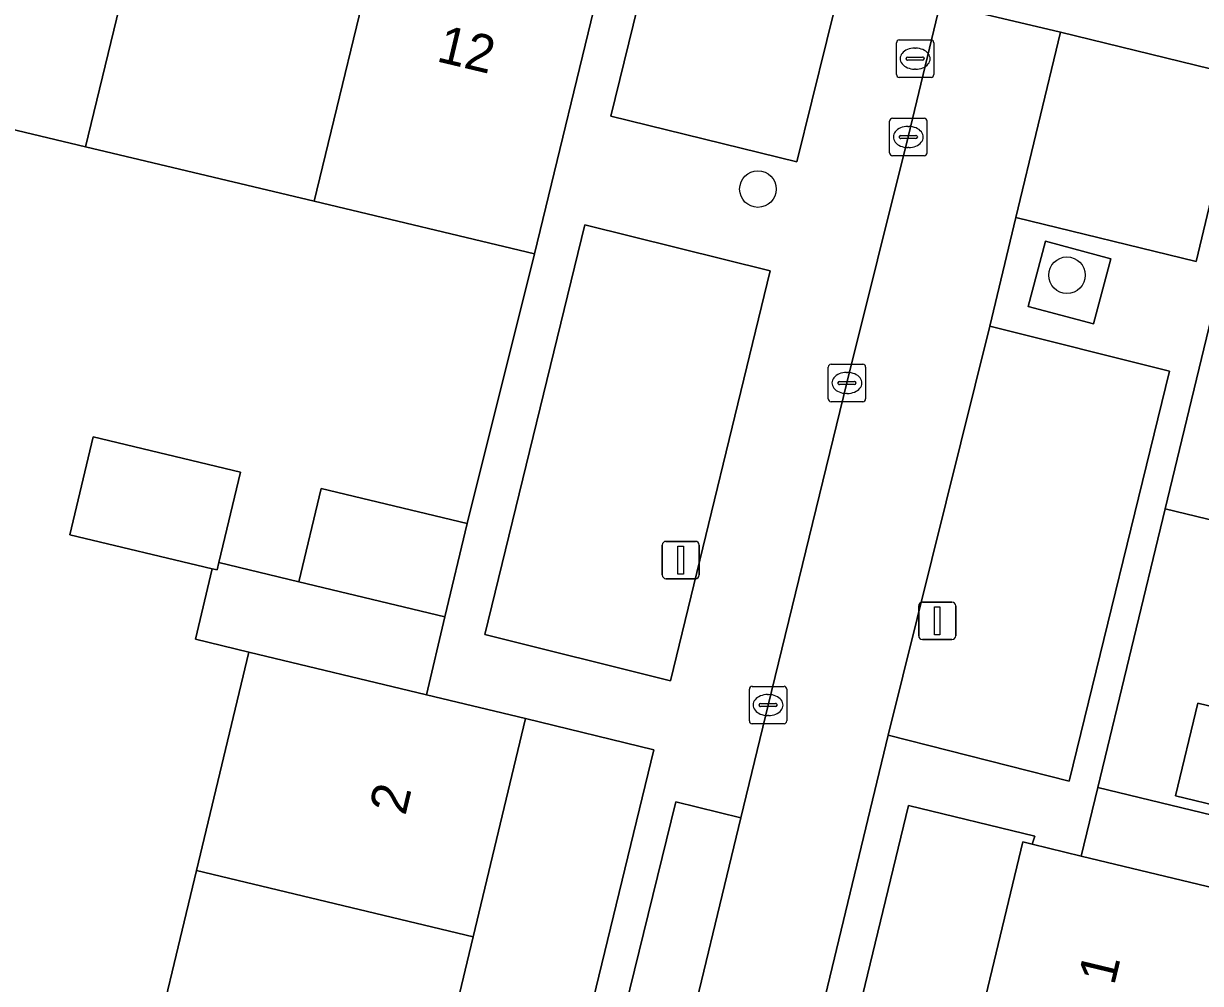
# Model space of a CAD drawing. Extents: x 162803 to 163818, y 381639 to 382475.
# Drawn here: x 163134.3 to 163165.81, y 382302.82 to 382328.5 of the extents above; entities that cross this region are included whole.
import ezdxf

# ---------------------------------------------------------------- set-up
doc = ezdxf.new("R2010")
doc.units = 0
for name, color, linetype in [('IMGEO_Boom', 7, 'Continuous'), ('IMGEO_Erf', 7, 'Continuous'), ('IMGEO_Groenvoorziening', 7, 'Continuous'), ('IMGEO_Kolk', 7, 'Continuous'), ('IMGEO_Lichtmast', 7, 'Continuous'), ('IMGEO_Muur', 7, 'Continuous'), ('IMGEO_Pand', 7, 'Continuous'), ('IMGEO_Pand_nummerreeks', 7, 'Continuous'), ('IMGEO_Parkeervlak_open', 7, 'Continuous'), ('IMGEO_Rijbaan_lokaal_open', 7, 'Continuous'), ('IMGEO_Rioolput', 7, 'Continuous'), ('IMGEO_Voetpad_open', 7, 'Continuous')]:
    doc.layers.add(name, color=color, linetype=linetype)

msp = doc.modelspace()

# ---------------------------------------------------------------- linework, layer by layer
at = {"layer": 'IMGEO_Boom'}
for centre in [(163153.96, 382324.072), (163162.234, 382321.768)]:
    msp.add_circle(centre, 0.489, dxfattribs=at)
at = {"layer": 'IMGEO_Erf'}
for points in [[(163137.51, 382299.932), (163138.927, 382305.841), (163140.328, 382311.683), (163138.901, 382312.025), (163139.353, 382313.911), (163135.54, 382314.821), (163136.165, 382317.441), (163140.107, 382316.5), (163139.53, 382314.08), (163141.667, 382313.567), (163142.265, 382316.061), (163146.18, 382315.122), (163147.979, 382322.337), (163142.076, 382323.745), (163135.958, 382325.205), (163130.086, 382326.605)], [(163170.946, 382314.044), (163164.865, 382315.515), (163163.061, 382308.056), (163184.008, 382302.99)], [(163137.011, 382250.814), (163151.17, 382309.066), (163147.739, 382309.906), (163146.338, 382304.063), (163144.921, 382298.154), (163143.552, 382292.448), (163142.148, 382286.591), (163140.708, 382280.587), (163139.316, 382274.782), (163137.911, 382268.926), (163136.518, 382263.116), (163135.102, 382257.214)]]:
    msp.add_lwpolyline(points, dxfattribs=at)
for points in [[(163169.129, 382306.875), (163165.137, 382307.839), (163165.736, 382310.318), (163169.728, 382309.354)], [(163154.012, 382277.422), (163155.425, 382283.276), (163156.897, 382289.378), (163158.25, 382294.983), (163159.675, 382300.888), (163161.054, 382306.603), (163161.303, 382306.543), (163161.374, 382306.761), (163157.996, 382307.58), (163144.039, 382250), (163143.732, 382248.734), (163146.893, 382247.921), (163147.395, 382250), (163148.351, 382253.961), (163149.715, 382259.613), (163151.151, 382265.563), (163152.6, 382271.569)]]:
    msp.add_lwpolyline(points, close=True, dxfattribs=at)
at = {"layer": 'IMGEO_Groenvoorziening'}
msp.add_lwpolyline([(163162.944, 382320.464), (163163.411, 382322.207), (163161.661, 382322.676), (163161.194, 382320.933)], close=True, dxfattribs=at)
at = {"layer": 'IMGEO_Kolk'}
for p, q in [((163157.486, 382325.04), (163157.486, 382325.892)), ((163157.561, 382325.966), (163158.413, 382325.966)), ((163158.487, 382325.892), (163158.487, 382325.04)), ((163157.788, 382325.509), (163158.186, 382325.509)), ((163157.974, 382325.746), (163157.999, 382325.746)), ((163157.745, 382325.46), (163157.745, 382325.472)), ((163158.183, 382325.423), (163157.785, 382325.423)), ((163158.229, 382325.472), (163158.229, 382325.46)), ((163158.413, 382324.966), (163157.561, 382324.966)), ((163157.997, 382325.186), (163157.972, 382325.186)), ((163155.843, 382318.458), (163155.843, 382319.31)), ((163155.918, 382319.384), (163156.77, 382319.384)), ((163156.844, 382319.31), (163156.844, 382318.458)), ((163156.102, 382318.878), (163156.102, 382318.89)), ((163156.145, 382318.927), (163156.543, 382318.927)), ((163156.331, 382319.164), (163156.356, 382319.164)), ((163156.586, 382318.89), (163156.586, 382318.878)), ((163156.54, 382318.841), (163156.142, 382318.841)), ((163156.354, 382318.604), (163156.329, 382318.604)), ((163156.77, 382318.384), (163155.918, 382318.384)), ((163153.807, 382310.767), (163154.659, 382310.767)), ((163153.732, 382309.841), (163153.732, 382310.693)), ((163154.22, 382310.547), (163154.245, 382310.547)), ((163154.733, 382310.693), (163154.733, 382309.841)), ((163153.991, 382310.261), (163153.991, 382310.273)), ((163154.429, 382310.224), (163154.031, 382310.224)), ((163154.034, 382310.31), (163154.432, 382310.31)), ((163154.475, 382310.273), (163154.475, 382310.261)), ((163154.659, 382309.767), (163153.807, 382309.767)), ((163154.243, 382309.987), (163154.218, 382309.987))]:
    msp.add_line(p, q, dxfattribs=at)
for points in [[(163157.486, 382325.04), (163157.486, 382325.892)], [(163157.561, 382325.966), (163158.413, 382325.966)], [(163158.487, 382325.892), (163158.487, 382325.04)], [(163158.413, 382324.966), (163157.561, 382324.966)], [(163155.843, 382318.458), (163155.843, 382319.31)], [(163155.918, 382319.384), (163156.77, 382319.384)], [(163156.844, 382319.31), (163156.844, 382318.458)], [(163156.77, 382318.384), (163155.918, 382318.384)], [(163153.807, 382310.767), (163154.659, 382310.767)], [(163153.732, 382309.841), (163153.732, 382310.693)], [(163154.733, 382310.693), (163154.733, 382309.841)], [(163154.659, 382309.767), (163153.807, 382309.767)]]:
    msp.add_lwpolyline(points, dxfattribs=at)
for centre, radius, start, end in [((163157.563, 382325.89), 0.0765, 91.552, 178.448), ((163157.563, 382325.89), 0.0765, 91.552, 178.448), ((163158.411, 382325.89), 0.0765, 1.552, 88.448), ((163158.411, 382325.89), 0.0765, 1.552, 88.448), ((163157.785, 382325.469), 0.0403, 85.8775, 175.7526), ((163158.19, 382325.471), 0.0386, 1.7309, 96.639), ((163157.782, 382325.459), 0.0366, 178.938, 274.7102), ((163158.186, 382325.466), 0.043, 264.8664, 352.4533), ((163157.563, 382325.042), 0.0765, 181.552, 268.448), ((163157.563, 382325.042), 0.0765, 181.552, 268.448), ((163158.411, 382325.042), 0.0765, 271.552, 358.448), ((163158.411, 382325.042), 0.0765, 271.552, 358.448), ((163155.92, 382319.308), 0.0765, 91.552, 178.448), ((163155.92, 382319.308), 0.0765, 91.552, 178.448), ((163156.768, 382319.308), 0.0765, 1.552, 88.448), ((163156.768, 382319.308), 0.0765, 1.552, 88.448), ((163156.142, 382318.887), 0.0403, 85.8775, 175.7526), ((163156.547, 382318.889), 0.0386, 1.7309, 96.639), ((163156.139, 382318.877), 0.0366, 178.938, 274.7102), ((163156.543, 382318.884), 0.043, 264.8664, 352.4533), ((163155.92, 382318.46), 0.0765, 181.552, 268.448), ((163155.92, 382318.46), 0.0765, 181.552, 268.448), ((163156.768, 382318.46), 0.0765, 271.552, 358.448), ((163156.768, 382318.46), 0.0765, 271.552, 358.448), ((163153.809, 382310.691), 0.0765, 91.552, 178.448), ((163153.809, 382310.691), 0.0765, 91.552, 178.448), ((163154.657, 382310.691), 0.0765, 1.552, 88.448), ((163154.657, 382310.691), 0.0765, 1.552, 88.448), ((163154.031, 382310.27), 0.0403, 85.8775, 175.7526), ((163154.028, 382310.26), 0.0366, 178.938, 274.7102), ((163154.432, 382310.267), 0.043, 264.8664, 352.4533), ((163154.436, 382310.272), 0.0386, 1.7309, 96.639), ((163153.809, 382309.843), 0.0765, 181.552, 268.448), ((163153.809, 382309.843), 0.0765, 181.552, 268.448), ((163154.657, 382309.843), 0.0765, 271.552, 358.448), ((163154.657, 382309.843), 0.0765, 271.552, 358.448)]:
    msp.add_arc(centre, radius, start, end, dxfattribs=at)
for centre, major_axis, ratio, start_param, end_param in [((163157.973, 382325.466), (-0.387, 0.002), 0.722429, 4.712389, 7.853982), ((163157.998, 382325.466), (-0.39, 0.002), 0.717154, 1.570796, 4.712389), ((163156.33, 382318.884), (-0.387, 0.002), 0.722429, 4.712389, 7.853982), ((163156.355, 382318.884), (-0.39, 0.002), 0.717154, 1.570796, 4.712389), ((163154.219, 382310.267), (-0.387, 0.002), 0.722429, 4.712389, 7.853982), ((163154.244, 382310.267), (-0.39, 0.002), 0.717154, 1.570796, 4.712389)]:
    msp.add_ellipse(centre, major_axis=major_axis, ratio=ratio, start_param=start_param, end_param=end_param, dxfattribs=at)
at = {"layer": 'IMGEO_Lichtmast'}
for p, q in [((163151.399, 382313.747), (163151.399, 382314.547)), ((163151.399, 382314.547), (163151.399, 382313.747)), ((163151.499, 382314.647), (163152.289, 382314.647)), ((163152.289, 382314.647), (163151.499, 382314.647)), ((163152.389, 382314.547), (163152.389, 382313.747)), ((163152.389, 382313.747), (163152.389, 382314.547)), ((163152.289, 382313.647), (163151.499, 382313.647)), ((163151.499, 382313.647), (163152.289, 382313.647)), ((163158.265, 382312.12), (163158.265, 382312.92)), ((163158.265, 382312.92), (163158.265, 382312.12)), ((163158.365, 382313.02), (163159.155, 382313.02)), ((163159.155, 382313.02), (163158.365, 382313.02)), ((163159.255, 382312.92), (163159.255, 382312.12)), ((163159.255, 382312.12), (163159.255, 382312.92)), ((163159.155, 382312.02), (163158.365, 382312.02)), ((163158.365, 382312.02), (163159.155, 382312.02))]:
    msp.add_line(p, q, dxfattribs=at)
for points in [[(163151.819, 382314.522), (163151.969, 382314.522), (163151.969, 382313.772), (163151.819, 382313.772), (163151.819, 382314.522)], [(163158.685, 382312.895), (163158.835, 382312.895), (163158.835, 382312.145), (163158.685, 382312.145), (163158.685, 382312.895)]]:
    msp.add_lwpolyline(points, dxfattribs=at)
for centre, start, end in [((163151.499, 382314.547), 90, 180), ((163151.499, 382314.547), 90, 180), ((163152.289, 382314.547), 0, 90), ((163152.289, 382314.547), 360, 90), ((163151.499, 382313.747), 180, 270), ((163151.499, 382313.747), 180, 270), ((163152.289, 382313.747), 270, 0), ((163152.289, 382313.747), 270, 0), ((163158.365, 382312.92), 90, 180), ((163158.365, 382312.92), 90, 180), ((163159.155, 382312.92), 0, 90), ((163159.155, 382312.92), 360, 90), ((163158.365, 382312.12), 180, 270), ((163158.365, 382312.12), 180, 270), ((163159.155, 382312.12), 270, 0), ((163159.155, 382312.12), 270, 0)]:
    msp.add_arc(centre, 0.1, start, end, dxfattribs=at)
at = {"layer": 'IMGEO_Muur'}
for points in [[(163146.18, 382315.122), (163147.979, 382322.337)], [(163164.865, 382315.515), (163163.126, 382308.325)]]:
    msp.add_lwpolyline(points, dxfattribs=at)
at = {"layer": 'IMGEO_Pand'}
for points in [[(163137.772, 382332.67), (163131.9, 382334.068), (163130.086, 382326.605), (163135.958, 382325.205)], [(163137.772, 382332.67), (163135.958, 382325.205), (163142.076, 382323.745), (163143.891, 382331.212)], [(163143.891, 382331.212), (163142.076, 382323.745), (163147.979, 382322.337), (163149.794, 382329.806)], [(163173.371, 382324.081), (163167.289, 382325.55), (163165.508, 382318.171), (163164.865, 382315.515), (163170.946, 382314.044), (163171.589, 382316.702)], [(163135.54, 382314.821), (163139.353, 382313.911), (163139.482, 382313.88), (163139.53, 382314.08), (163140.107, 382316.5), (163136.165, 382317.441)], [(163145.582, 382312.628), (163146.18, 382315.122), (163142.265, 382316.061), (163141.667, 382313.567)], [(163138.927, 382305.841), (163146.338, 382304.063), (163147.739, 382309.906), (163145.083, 382310.543), (163140.328, 382311.683)], [(163169.129, 382306.875), (163169.728, 382309.354), (163165.736, 382310.318), (163165.137, 382307.839)], [(163159.675, 382300.888), (163167.074, 382299.103), (163168.453, 382304.819), (163162.618, 382306.226), (163161.303, 382306.543), (163161.054, 382306.603)], [(163144.921, 382298.154), (163146.338, 382304.063), (163138.927, 382305.841), (163137.51, 382299.932)]]:
    msp.add_lwpolyline(points, close=True, dxfattribs=at)
at = {"layer": 'IMGEO_Parkeervlak_open'}
for points in [[(163156.205, 382329.677), (163151.219, 382330.903), (163150.02, 382326.027), (163155.006, 382324.801)], [(163160.861, 382323.309), (163165.692, 382322.136), (163166.876, 382327.097), (163162.058, 382328.272)], [(163151.624, 382310.917), (163154.289, 382321.881), (163149.323, 382323.114), (163146.649, 382312.151)], [(163157.45, 382309.459), (163162.297, 382308.228), (163164.976, 382319.203), (163160.171, 382320.403)], [(163153.503, 382307.253), (163151.764, 382307.677), (163149.171, 382297.147), (163150.941, 382296.711), (163151.885, 382300.558)]]:
    msp.add_lwpolyline(points, close=True, dxfattribs=at)
at = {"layer": 'IMGEO_Rijbaan_lokaal_open'}
for points in [[(163157.45, 382309.459), (163160.171, 382320.403), (163160.861, 382323.309), (163162.058, 382328.272), (163158.84, 382329.032), (163157.986, 382325.467), (163156.343, 382318.884), (163154.231, 382310.267), (163153.503, 382307.253), (163151.885, 382300.558), (163150.941, 382296.711), (163150.593, 382295.245), (163148.02, 382284.701), (163147.649, 382283.226), (163145.094, 382272.703), (163144.748, 382271.241), (163144.006, 382268.167), (163142.171, 382260.712), (163141.812, 382259.252), (163140.24, 382252.604), (163139.594, 382250), (163139.247, 382248.603)], [(163142.397, 382247.069), (163143.104, 382250), (163157.45, 382309.459)]]:
    msp.add_lwpolyline(points, dxfattribs=at)
at = {"layer": 'IMGEO_Rioolput'}
for p, q in [((163157.744, 382328.062), (163158.596, 382328.062)), ((163157.669, 382327.136), (163157.669, 382327.988)), ((163158.157, 382327.842), (163158.182, 382327.842)), ((163158.67, 382327.988), (163158.67, 382327.136)), ((163157.928, 382327.556), (163157.928, 382327.568)), ((163158.366, 382327.519), (163157.968, 382327.519)), ((163157.971, 382327.605), (163158.369, 382327.605)), ((163158.412, 382327.568), (163158.412, 382327.556)), ((163158.18, 382327.282), (163158.155, 382327.282)), ((163158.596, 382327.062), (163157.744, 382327.062))]:
    msp.add_line(p, q, dxfattribs=at)
for points in [[(163157.744, 382328.062), (163158.596, 382328.062)], [(163157.669, 382327.136), (163157.669, 382327.988)], [(163158.67, 382327.988), (163158.67, 382327.136)], [(163158.596, 382327.062), (163157.744, 382327.062)]]:
    msp.add_lwpolyline(points, dxfattribs=at)
for centre, radius, start, end in [((163157.746, 382327.986), 0.0765, 91.552, 178.448), ((163157.746, 382327.986), 0.0765, 91.552, 178.448), ((163158.594, 382327.986), 0.0765, 1.552, 88.448), ((163158.594, 382327.986), 0.0765, 1.552, 88.448), ((163157.968, 382327.565), 0.0403, 85.8775, 175.7526), ((163157.965, 382327.555), 0.0366, 178.938, 274.7102), ((163158.369, 382327.562), 0.043, 264.8664, 352.4533), ((163158.373, 382327.567), 0.0386, 1.7309, 96.639), ((163157.746, 382327.138), 0.0765, 181.552, 268.448), ((163157.746, 382327.138), 0.0765, 181.552, 268.448), ((163158.594, 382327.138), 0.0765, 271.552, 358.448), ((163158.594, 382327.138), 0.0765, 271.552, 358.448)]:
    msp.add_arc(centre, radius, start, end, dxfattribs=at)
for centre, major_axis, ratio, start_param, end_param in [((163158.156, 382327.562), (-0.387, 0.002), 0.722429, 4.712389, 7.853982), ((163158.181, 382327.562), (-0.39, 0.002), 0.717154, 1.570796, 4.712389)]:
    msp.add_ellipse(centre, major_axis=major_axis, ratio=ratio, start_param=start_param, end_param=end_param, dxfattribs=at)
at = {"layer": 'IMGEO_Voetpad_open'}
for points in [[(163108.877, 382341.135), (163114.317, 382339.892), (163150.106, 382331.192), (163151.219, 382330.903), (163156.205, 382329.677), (163158.84, 382329.032), (163162.058, 382328.272), (163166.876, 382327.097), (163167.673, 382326.978), (163203.509, 382318.352), (163211.924, 382316.587)], [(163157.986, 382325.467), (163158.84, 382329.032), (163156.205, 382329.677), (163155.006, 382324.801), (163150.02, 382326.027), (163151.219, 382330.903), (163150.106, 382331.192), (163149.794, 382329.806), (163147.979, 382322.337), (163146.18, 382315.122), (163145.582, 382312.628), (163145.083, 382310.543), (163147.739, 382309.906), (163151.17, 382309.066), (163137.011, 382250.814), (163136.747, 382250.336), (163136.536, 382250), (163135.523, 382248.664), (163139.012, 382247.86)], [(163139.247, 382248.603), (163137.515, 382249.041), (163137.748, 382250), (163140.099, 382259.655), (163141.812, 382259.252), (163142.171, 382260.712), (163140.456, 382261.14), (163142.996, 382271.662), (163144.748, 382271.241), (163145.094, 382272.703), (163143.364, 382273.124), (163145.921, 382283.659), (163147.649, 382283.226), (163148.02, 382284.701), (163146.287, 382285.125), (163148.848, 382295.668), (163150.593, 382295.245), (163150.941, 382296.711), (163149.171, 382297.147), (163151.764, 382307.677), (163153.503, 382307.253), (163154.231, 382310.267), (163156.343, 382318.884), (163157.986, 382325.467)]]:
    msp.add_lwpolyline(points, dxfattribs=at)
for points in [[(163167.289, 382325.55), (163167.673, 382326.978), (163166.876, 382327.097), (163165.692, 382322.136), (163160.861, 382323.309), (163160.171, 382320.403), (163164.976, 382319.203), (163162.297, 382308.228), (163157.45, 382309.459), (163143.104, 382250), (163142.397, 382247.069), (163143.272, 382246.834), (163143.732, 382248.734), (163144.039, 382250), (163157.996, 382307.58), (163161.374, 382306.761), (163161.303, 382306.543), (163162.618, 382306.226), (163163.061, 382308.056), (163164.865, 382315.515), (163165.508, 382318.171)], [(163154.289, 382321.881), (163151.624, 382310.917), (163146.649, 382312.151), (163149.323, 382323.114)], [(163162.944, 382320.464), (163161.194, 382320.933), (163161.661, 382322.676), (163163.411, 382322.207)], [(163145.582, 382312.628), (163141.667, 382313.567), (163139.53, 382314.08), (163139.482, 382313.88), (163139.353, 382313.911), (163138.901, 382312.025), (163140.328, 382311.683), (163145.083, 382310.543)], [(163181.603, 382292.88), (163182.159, 382295.184), (163182.997, 382298.803), (163183.553, 382301.107), (163184.008, 382302.99), (163163.061, 382308.056), (163162.618, 382306.226), (163168.453, 382304.819), (163179.856, 382302.069), (163174.748, 382280.968), (163174.783, 382280.961), (163174.209, 382278.584), (163174.173, 382278.593), (163173.283, 382274.916), (163177.079, 382273.933), (163178.727, 382280.951), (163179.346, 382283.527)]]:
    msp.add_lwpolyline(points, close=True, dxfattribs=at)

# ---------------------------------------------------------------- texts
at = {"layer": 'IMGEO_Pand_nummerreeks'}
for s, rotation, p in [('12', 346.6017, (163145.326, 382327.498)), ('2', 76.514, (163144.519, 382307.288)), ('1', 76.4329, (163163.496, 382302.743))]:
    msp.add_text(s, height=1, rotation=rotation, dxfattribs=at).set_placement(p)

doc.saveas('drawing.dxf')
